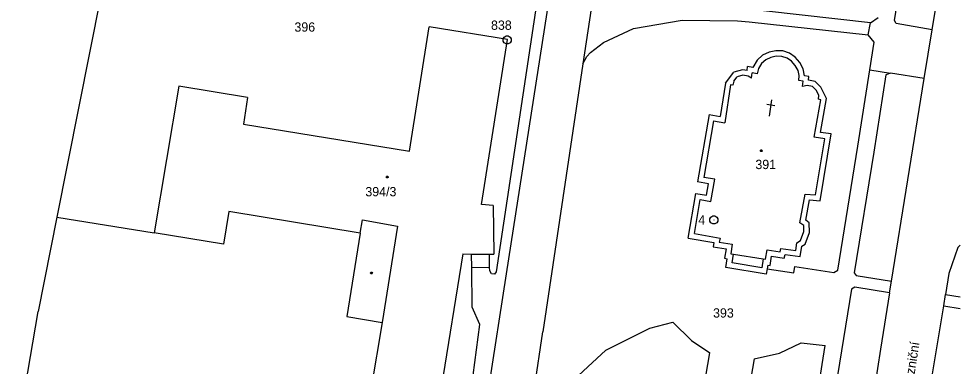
# Model space of a CAD drawing. Extents: x -851495 to -851222, y -1010479 to -1010202.
# Drawn here: x -851399.9 to -851227.5, y -1010362.9 to -1010299.4 of the extents above; entities that cross this region are included whole.
import ezdxf

# ---------------------------------------------------------------- set-up
doc = ezdxf.new("R2010")
doc.units = 0
for name, color, linetype in [('1', 7, 'Continuous'), ('12', 7, 'Continuous'), ('2', 7, 'Continuous'), ('4', 7, 'Continuous'), ('5', 7, 'Continuous'), ('7', 7, 'Continuous'), ('8', 7, 'Continuous')]:
    doc.layers.add(name, color=color, linetype=linetype)

# ---------------------------------------------------------------- blocks, each defined once
blk = doc.blocks.new('101')
blk.add_line((-0.05, 0), (0.05, 0))
blk.add_lwpolyline([(0.19, 0.72), (0.53, 0.53), (0.72, 0.19), (0.72, -0.2), (0.53, -0.54), (0.19, -0.73), (-0.2, -0.73), (-0.54, -0.54), (-0.73, -0.2), (-0.73, 0.19), (-0.54, 0.53), (-0.2, 0.72), (0.19, 0.72)])
blk = doc.blocks.new('402')
blk.add_lwpolyline([(0.09, 0.15), (0.18, 0), (0.09, -0.15), (-0.09, -0.15), (-0.18, 0), (-0.09, 0.15), (0.09, 0.15)])
blk = doc.blocks.new('4091')
for p, q in [((0.75, 2), (-0.75, 2)), ((0, 0), (0, 3))]:
    blk.add_line(p, q)
blk = doc.blocks.new('404')
blk.add_lwpolyline([(0, 0.17), (0.1, 0.15), (0.15, 0.06), (0.17, 0), (0.15, -0.09), (0.07, -0.16), (0, -0.17), (-0.09, -0.14), (-0.15, -0.08), (-0.17, 0), (-0.15, 0.09), (-0.07, 0.16), (0, 0.17)])

msp = doc.modelspace()

# ---------------------------------------------------------------- linework, layer by layer
at = {"layer": '1'}
for p, q in [((-851232.63, -1010301.37), (-851230.79, -1010290.13)), ((-851384.52, -1010293.11), (-851392.95, -1010335.63)), ((-851304.33, -1010291.66), (-851312.49, -1010345.66)), ((-851294.79, -1010295.43), (-851296.61, -1010307.61)), ((-851287.35, -1010301.15), (-851278.41, -1010299.63)), ((-851278.41, -1010299.63), (-851268.29, -1010299.7)), ((-851268.29, -1010299.7), (-851266.13, -1010299.94)), ((-851266.13, -1010299.94), (-851244.35, -1010302.27)), ((-851328.39, -1010323.57), (-851324.75, -1010300.84)), ((-851310.4, -1010303.13), (-851324.75, -1010300.84)), ((-851292.8, -1010303.71), (-851287.35, -1010301.15)), ((-851234.08, -1010310.3), (-851232.63, -1010301.37)), ((-851315.15, -1010333.34), (-851310.4, -1010303.13)), ((-851243.25, -1010303.62), (-851244.35, -1010302.27)), ((-851295.24, -1010305.54), (-851292.8, -1010303.71)), ((-851261.29, -1010305.19), (-851262.5, -1010305.46)), ((-851259.96, -1010305.23), (-851261.29, -1010305.19)), ((-851258.74, -1010305.66), (-851259.96, -1010305.23)), ((-851244.05, -1010308.69), (-851243.25, -1010303.62)), ((-851296.61, -1010307.61), (-851295.91, -1010306.24)), ((-851295.91, -1010306.24), (-851295.24, -1010305.54)), ((-851264.66, -1010306.95), (-851265.49, -1010308.25)), ((-851263.69, -1010305.99), (-851264.66, -1010306.95)), ((-851262.5, -1010305.46), (-851263.69, -1010305.99)), ((-851257.72, -1010306.37), (-851258.74, -1010305.66)), ((-851256.87, -1010307.34), (-851257.72, -1010306.37)), ((-851296.61, -1010307.61), (-851303.96, -1010356.63)), ((-851267.4, -1010308.66), (-851268.94, -1010309.13)), ((-851266.54, -1010308.79), (-851267.4, -1010308.66)), ((-851266.54, -1010308.79), (-851266.46, -1010308.09)), ((-851265.49, -1010308.25), (-851266.46, -1010308.09)), ((-851256.25, -1010308.49), (-851256.87, -1010307.34)), ((-851255.99, -1010309.79), (-851256.25, -1010308.49)), ((-851244.05, -1010308.69), (-851240.28, -1010309.3)), ((-851270.51, -1010311.14), (-851268.94, -1010309.13)), ((-851255.19, -1010309.92), (-851255.99, -1010309.79)), ((-851255.26, -1010310.59), (-851255.19, -1010309.92)), ((-851234.08, -1010310.3), (-851240.28, -1010309.3)), ((-851240.07, -1010347.32), (-851234.08, -1010310.3)), ((-851370.64, -1010311.68), (-851375.15, -1010338.51)), ((-851358.02, -1010313.76), (-851370.64, -1010311.68)), ((-851270.51, -1010311.14), (-851271.44, -1010317.21)), ((-851254.08, -1010310.82), (-851255.26, -1010310.59)), ((-851253.01, -1010311.86), (-851254.08, -1010310.82)), ((-851251.99, -1010313.96), (-851253.01, -1010311.86)), ((-851358.02, -1010313.76), (-851358.77, -1010318.6)), ((-851253.1, -1010320.17), (-851251.99, -1010313.96)), ((-851273.5, -1010316.88), (-851275.59, -1010329.19)), ((-851273.5, -1010316.88), (-851271.44, -1010317.21)), ((-851358.77, -1010318.6), (-851328.39, -1010323.57)), ((-851253.15, -1010332.64), (-851251.15, -1010320.42)), ((-851251.15, -1010320.42), (-851253.1, -1010320.17)), ((-851273.61, -1010329.53), (-851275.59, -1010329.19)), ((-851273.96, -1010331.61), (-851273.61, -1010329.53)), ((-851277.32, -1010339.47), (-851275.94, -1010331.28)), ((-851275.94, -1010331.28), (-851273.96, -1010331.61)), ((-851255.75, -1010336.21), (-851255.09, -1010332.47)), ((-851255.09, -1010332.47), (-851253.15, -1010332.64)), ((-851361.47, -1010334.58), (-851362.46, -1010340.6)), ((-851337.39, -1010338.59), (-851361.47, -1010334.58)), ((-851313.04, -1010333.49), (-851315.15, -1010333.34)), ((-851313.04, -1010333.49), (-851312.93, -1010342.39)), ((-851392.95, -1010335.63), (-851396.37, -1010352.9)), ((-851392.95, -1010335.63), (-851375.15, -1010338.51)), ((-851255.14, -1010336.67), (-851255.75, -1010336.21)), ((-851255.11, -1010338.45), (-851255.14, -1010336.67)), ((-851362.46, -1010340.6), (-851375.15, -1010338.51)), ((-851337.39, -1010338.59), (-851339.82, -1010353.78)), ((-851277.32, -1010339.47), (-851272.64, -1010340.27)), ((-851255.9, -1010340.6), (-851255.11, -1010338.45)), ((-851272.64, -1010340.27), (-851272.77, -1010341.05)), ((-851272.77, -1010341.05), (-851270.39, -1010341.42)), ((-851270.39, -1010341.42), (-851270.66, -1010343.15)), ((-851256.79, -1010342.82), (-851256.49, -1010340.95)), ((-851256.49, -1010340.95), (-851255.9, -1010340.6)), ((-851313.71, -1010344.85), (-851313.7, -1010342.39)), ((-851313.7, -1010342.39), (-851312.93, -1010342.39)), ((-851270.66, -1010343.15), (-851270.18, -1010343.23)), ((-851270.44, -1010344.82), (-851270.18, -1010343.23)), ((-851262.3, -1010344.47), (-851262.03, -1010342.75)), ((-851262.03, -1010342.75), (-851259.73, -1010343.11)), ((-851259.73, -1010343.11), (-851259.58, -1010342.45)), ((-851259.58, -1010342.45), (-851256.79, -1010342.82)), ((-851313.71, -1010344.85), (-851316.97, -1010344.93)), ((-851316.91, -1010352.07), (-851316.97, -1010344.93)), ((-851313.66, -1010345.45), (-851313.71, -1010344.85)), ((-851263.02, -1010346.03), (-851270.44, -1010344.82)), ((-851262.76, -1010344.4), (-851262.87, -1010345.08)), ((-851262.76, -1010344.4), (-851262.3, -1010344.47)), ((-851313.37, -1010345.99), (-851313.66, -1010345.45)), ((-851312.82, -1010346.06), (-851313.37, -1010345.99)), ((-851312.49, -1010345.66), (-851312.82, -1010346.06)), ((-851262.87, -1010345.08), (-851263.02, -1010346.03)), ((-851240.43, -1010349.46), (-851240.07, -1010347.32)), ((-851240.43, -1010349.46), (-851242.07, -1010359.77)), ((-851399.92, -1010373.67), (-851396.37, -1010352.9)), ((-851315.46, -1010355.26), (-851316.91, -1010352.07)), ((-851339.82, -1010353.78), (-851333.35, -1010354.87)), ((-851333.35, -1010354.87), (-851335.38, -1010366.85)), ((-851318.65, -1010378.9), (-851315.46, -1010355.26)), ((-851305.87, -1010369.39), (-851303.96, -1010356.63)), ((-851242.07, -1010359.77), (-851246.84, -1010389.17))]:
    msp.add_line(p, q, dxfattribs=at)
at = {"layer": '12'}
for p, q in [((-851328.39, -1010323.57), (-851324.75, -1010300.84)), ((-851310.4, -1010303.13), (-851324.75, -1010300.84)), ((-851315.15, -1010333.34), (-851310.4, -1010303.13)), ((-851263.12, -1010306.83), (-851263.86, -1010307.56)), ((-851262.19, -1010306.42), (-851263.12, -1010306.83)), ((-851261.21, -1010306.2), (-851262.19, -1010306.42)), ((-851260.15, -1010306.23), (-851261.21, -1010306.2)), ((-851259.19, -1010306.56), (-851260.15, -1010306.23)), ((-851258.39, -1010307.12), (-851259.19, -1010306.56)), ((-851264.41, -1010308.42), (-851264.67, -1010309.41)), ((-851263.86, -1010307.56), (-851264.41, -1010308.42)), ((-851257.71, -1010307.9), (-851258.39, -1010307.12)), ((-851257.2, -1010308.83), (-851257.71, -1010307.9)), ((-851268.96, -1010310.78), (-851268.34, -1010309.99)), ((-851267.33, -1010309.68), (-851268.34, -1010309.99)), ((-851266.34, -1010309.83), (-851267.33, -1010309.68)), ((-851265.7, -1010310.21), (-851266.34, -1010309.83)), ((-851265.7, -1010310.21), (-851265.59, -1010309.25)), ((-851264.67, -1010309.41), (-851265.59, -1010309.25)), ((-851257.02, -1010309.75), (-851257.2, -1010308.83)), ((-851257.05, -1010310.64), (-851257.02, -1010309.75)), ((-851370.64, -1010311.68), (-851375.15, -1010338.51)), ((-851358.02, -1010313.76), (-851370.64, -1010311.68)), ((-851269.55, -1010311.45), (-851270.6, -1010318.36)), ((-851269.13, -1010311.5), (-851269.55, -1010311.45)), ((-851268.96, -1010310.78), (-851269.13, -1010311.5)), ((-851256.28, -1010310.76), (-851257.05, -1010310.64)), ((-851256.38, -1010311.75), (-851256.28, -1010310.76)), ((-851255.53, -1010311.56), (-851256.38, -1010311.75)), ((-851254.56, -1010311.75), (-851255.53, -1010311.56)), ((-851253.84, -1010312.45), (-851254.56, -1010311.75)), ((-851358.02, -1010313.76), (-851358.77, -1010318.6)), ((-851253.38, -1010313.4), (-851253.84, -1010312.45)), ((-851253.44, -1010314.08), (-851253.38, -1010313.4)), ((-851254.27, -1010321.03), (-851253.04, -1010314.16)), ((-851253.04, -1010314.16), (-851253.44, -1010314.08)), ((-851358.77, -1010318.6), (-851328.39, -1010323.57)), ((-851272.68, -1010318.03), (-851274.43, -1010328.37)), ((-851272.68, -1010318.03), (-851270.6, -1010318.36)), ((-851252.31, -1010321.28), (-851254.27, -1010321.03)), ((-851253.99, -1010331.56), (-851252.31, -1010321.28)), ((-851272.45, -1010328.71), (-851274.43, -1010328.37)), ((-851273.15, -1010332.76), (-851272.45, -1010328.71)), ((-851276.17, -1010338.65), (-851275.12, -1010332.43)), ((-851275.12, -1010332.43), (-851273.15, -1010332.76)), ((-851256.85, -1010336.64), (-851255.92, -1010331.4)), ((-851255.92, -1010331.4), (-851253.99, -1010331.56)), ((-851361.47, -1010334.58), (-851362.46, -1010340.6)), ((-851337.39, -1010338.59), (-851361.47, -1010334.58)), ((-851313.04, -1010333.49), (-851315.15, -1010333.34)), ((-851313.04, -1010333.49), (-851312.93, -1010342.39)), ((-851337.39, -1010338.59), (-851336.98, -1010336.14)), ((-851336.98, -1010336.14), (-851330.55, -1010337.26)), ((-851330.55, -1010337.26), (-851333.35, -1010354.87)), ((-851256.13, -1010337.18), (-851256.85, -1010336.64)), ((-851256.11, -1010338.28), (-851256.13, -1010337.18)), ((-851362.46, -1010340.6), (-851375.15, -1010338.51)), ((-851276.17, -1010338.65), (-851271.49, -1010339.45)), ((-851271.49, -1010339.45), (-851271.62, -1010340.22)), ((-851256.72, -1010339.93), (-851256.11, -1010338.28)), ((-851271.62, -1010340.22), (-851269.25, -1010340.59)), ((-851269.25, -1010340.59), (-851269.52, -1010342.32)), ((-851260.49, -1010341.98), (-851260.34, -1010341.34)), ((-851260.34, -1010341.34), (-851257.62, -1010341.7)), ((-851257.62, -1010341.7), (-851257.4, -1010340.33)), ((-851257.4, -1010340.33), (-851256.72, -1010339.93)), ((-851318.6, -1010342.35), (-851325.73, -1010386.47)), ((-851318.6, -1010342.35), (-851316.99, -1010342.4)), ((-851316.99, -1010342.4), (-851313.7, -1010342.39)), ((-851313.7, -1010342.39), (-851312.93, -1010342.39)), ((-851269.52, -1010342.32), (-851269.03, -1010342.4)), ((-851269.03, -1010342.4), (-851263.59, -1010343.26)), ((-851263.59, -1010343.26), (-851263.13, -1010343.33)), ((-851263.13, -1010343.33), (-851262.86, -1010341.61)), ((-851262.86, -1010341.61), (-851260.49, -1010341.98)), ((-851333.35, -1010354.87), (-851335.38, -1010366.85))]:
    msp.add_line(p, q, dxfattribs=at)
at = {"layer": '4'}
for p, q in [((-851239.52, -1010299.69), (-851234.68, -1010269.05)), ((-851302.19, -1010291.81), (-851310.67, -1010345.99)), ((-851243.92, -1010300.08), (-851269.5, -1010297.24)), ((-851244.35, -1010302.27), (-851243.92, -1010300.08)), ((-851243.92, -1010300.08), (-851242.55, -1010299.1)), ((-851239.24, -1010300.21), (-851239.52, -1010299.69)), ((-851232.63, -1010301.37), (-851239.24, -1010300.21)), ((-851263.12, -1010306.83), (-851263.86, -1010307.56)), ((-851262.19, -1010306.42), (-851263.12, -1010306.83)), ((-851261.21, -1010306.2), (-851262.19, -1010306.42)), ((-851260.15, -1010306.23), (-851261.21, -1010306.2)), ((-851259.19, -1010306.56), (-851260.15, -1010306.23)), ((-851258.39, -1010307.12), (-851259.19, -1010306.56)), ((-851264.41, -1010308.42), (-851264.67, -1010309.41)), ((-851263.86, -1010307.56), (-851264.41, -1010308.42)), ((-851257.71, -1010307.9), (-851258.39, -1010307.12)), ((-851257.2, -1010308.83), (-851257.71, -1010307.9)), ((-851246.23, -1010322.62), (-851244.05, -1010308.69)), ((-851268.96, -1010310.78), (-851268.34, -1010309.99)), ((-851267.33, -1010309.68), (-851268.34, -1010309.99)), ((-851266.34, -1010309.83), (-851267.33, -1010309.68)), ((-851265.7, -1010310.21), (-851266.34, -1010309.83)), ((-851265.7, -1010310.21), (-851265.59, -1010309.25)), ((-851264.67, -1010309.41), (-851265.59, -1010309.25)), ((-851257.02, -1010309.75), (-851257.2, -1010308.83)), ((-851257.05, -1010310.64), (-851257.02, -1010309.75)), ((-851241.09, -1010309.61), (-851243.33, -1010323.73)), ((-851240.28, -1010309.3), (-851241.09, -1010309.61)), ((-851269.55, -1010311.45), (-851270.6, -1010318.36)), ((-851269.13, -1010311.5), (-851269.55, -1010311.45)), ((-851268.96, -1010310.78), (-851269.13, -1010311.5)), ((-851256.28, -1010310.76), (-851257.05, -1010310.64)), ((-851256.38, -1010311.75), (-851256.28, -1010310.76)), ((-851255.53, -1010311.56), (-851256.38, -1010311.75)), ((-851254.56, -1010311.75), (-851255.53, -1010311.56)), ((-851253.84, -1010312.45), (-851254.56, -1010311.75)), ((-851253.38, -1010313.4), (-851253.84, -1010312.45)), ((-851253.44, -1010314.08), (-851253.38, -1010313.4)), ((-851254.27, -1010321.03), (-851253.04, -1010314.16)), ((-851253.04, -1010314.16), (-851253.44, -1010314.08)), ((-851272.68, -1010318.03), (-851274.43, -1010328.37)), ((-851272.68, -1010318.03), (-851270.6, -1010318.36)), ((-851252.31, -1010321.28), (-851254.27, -1010321.03)), ((-851253.99, -1010331.56), (-851252.31, -1010321.28)), ((-851249.92, -1010345.32), (-851246.23, -1010322.62)), ((-851243.33, -1010323.73), (-851246.92, -1010345.8)), ((-851272.45, -1010328.71), (-851274.43, -1010328.37)), ((-851273.15, -1010332.76), (-851272.45, -1010328.71)), ((-851276.17, -1010338.65), (-851275.12, -1010332.43)), ((-851275.12, -1010332.43), (-851273.15, -1010332.76)), ((-851256.85, -1010336.64), (-851255.92, -1010331.4)), ((-851255.92, -1010331.4), (-851253.99, -1010331.56)), ((-851337.39, -1010338.59), (-851336.98, -1010336.14)), ((-851336.98, -1010336.14), (-851330.55, -1010337.26)), ((-851330.55, -1010337.26), (-851333.35, -1010354.87)), ((-851256.13, -1010337.18), (-851256.85, -1010336.64)), ((-851256.11, -1010338.28), (-851256.13, -1010337.18)), ((-851276.17, -1010338.65), (-851271.49, -1010339.45)), ((-851271.49, -1010339.45), (-851271.62, -1010340.22)), ((-851256.72, -1010339.93), (-851256.11, -1010338.28)), ((-851271.62, -1010340.22), (-851269.25, -1010340.59)), ((-851269.25, -1010340.59), (-851269.52, -1010342.32)), ((-851260.49, -1010341.98), (-851260.34, -1010341.34)), ((-851260.34, -1010341.34), (-851257.62, -1010341.7)), ((-851257.62, -1010341.7), (-851257.4, -1010340.33)), ((-851257.4, -1010340.33), (-851256.72, -1010339.93)), ((-851227.95, -1010341.18), (-851229.55, -1010345.95)), ((-851227.5, -1010340.74), (-851227.95, -1010341.18)), ((-851318.6, -1010342.35), (-851325.73, -1010386.47)), ((-851318.6, -1010342.35), (-851316.99, -1010342.4)), ((-851316.99, -1010342.4), (-851313.7, -1010342.39)), ((-851316.97, -1010344.93), (-851316.99, -1010342.4)), ((-851269.52, -1010342.32), (-851269.03, -1010342.4)), ((-851269.29, -1010343.99), (-851269.03, -1010342.4)), ((-851269.03, -1010342.4), (-851263.59, -1010343.26)), ((-851263.59, -1010343.26), (-851263.85, -1010344.88)), ((-851263.59, -1010343.26), (-851263.13, -1010343.33)), ((-851263.13, -1010343.33), (-851262.86, -1010341.61)), ((-851262.86, -1010341.61), (-851260.49, -1010341.98)), ((-851263.85, -1010344.88), (-851269.29, -1010343.99)), ((-851257.94, -1010345.82), (-851257.77, -1010344.68)), ((-851257.77, -1010344.68), (-851250.65, -1010345.74)), ((-851310.67, -1010345.99), (-851317.33, -1010389.12)), ((-851262.87, -1010345.08), (-851257.94, -1010345.82)), ((-851250.65, -1010345.74), (-851249.92, -1010345.32)), ((-851246.92, -1010345.8), (-851246.54, -1010346.33)), ((-851246.54, -1010346.33), (-851240.07, -1010347.32)), ((-851229.55, -1010345.95), (-851230.19, -1010349.76)), ((-851246.77, -1010348.43), (-851247.42, -1010348.78)), ((-851240.43, -1010349.46), (-851246.77, -1010348.43)), ((-851247.42, -1010348.78), (-851254.68, -1010393.74)), ((-851230.49, -1010351.84), (-851230.19, -1010349.76)), ((-851230.19, -1010349.76), (-851227.5, -1010350.22)), ((-851232.08, -1010361.34), (-851230.49, -1010351.84)), ((-851230.49, -1010351.84), (-851227.5, -1010352.36)), ((-851284.36, -1010355.91), (-851280.11, -1010354.82)), ((-851280.11, -1010354.82), (-851276.74, -1010358.19)), ((-851292.42, -1010359.97), (-851284.36, -1010355.91)), ((-851276.74, -1010358.19), (-851273.38, -1010360.47)), ((-851260.6, -1010360.48), (-851256.61, -1010358.59)), ((-851256.61, -1010358.59), (-851252.25, -1010359.13)), ((-851301.31, -1010368.16), (-851292.42, -1010359.97)), ((-851283.86, -1010422.84), (-851273.38, -1010360.47)), ((-851265.21, -1010361.53), (-851260.6, -1010360.48)), ((-851257.76, -1010393.63), (-851252.25, -1010359.13)), ((-851265.21, -1010361.53), (-851276.04, -1010424.45)), ((-851236.92, -1010390.82), (-851232.08, -1010361.34))]:
    msp.add_line(p, q, dxfattribs=at)

# ---------------------------------------------------------------- block references
at = {"layer": '5', "rotation": -8.032025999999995}
msp.add_blockref('4091', (-851262.44, -1010317.14), dxfattribs=at)
at = {"layer": '5'}
for name, p in [('404', (-851263.9, -1010323.48)), ('404', (-851332.44, -1010328.29)), ('402', (-851335.34, -1010345.85))]:
    msp.add_blockref(name, p, dxfattribs=at)
at = {"layer": '8'}
for p in [(-851310.48, -1010303.22), (-851272.6, -1010336.14)]:
    msp.add_blockref('101', p, dxfattribs=at)

# ---------------------------------------------------------------- texts
at = {"layer": '2'}
for s, p in [('396', (-851349.44, -1010301.71)), ('391', (-851265.01, -1010326.84)), ('394/3', (-851336.45, -1010331.82)), ('393', (-851272.76, -1010354))]:
    msp.add_text(s, height=1.7, dxfattribs=at).set_placement(p)
at = {"layer": '7'}
msp.add_text('Železniční', height=1.7, rotation=81.131, dxfattribs=at).set_placement((-851236.53, -1010368.81))
at = {"layer": '8'}
for s, p in [('838', (-851313.43, -1010301.37)), ('4', (-851275.47, -1010336.99))]:
    msp.add_text(s, height=1.7, dxfattribs=at).set_placement(p)

doc.saveas('drawing.dxf')
